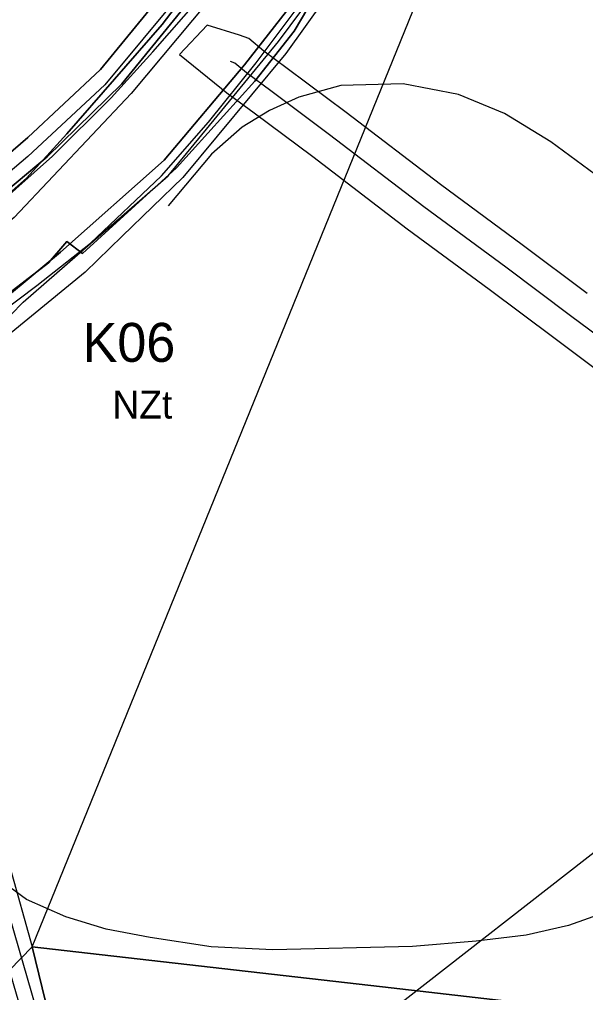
# Model space of a CAD drawing. Extents: x -758499 to -754160, y -1175205 to -1172032.
# Drawn here: x -756267 to -756063.4, y -1173950.7 to -1173601 of the extents above; entities that cross this region are included whole.
import ezdxf

# ---------------------------------------------------------------- set-up
doc = ezdxf.new("R2010")
doc.units = 0
for name, color, linetype in [('A012_RegLidArch_p', 7, 'Continuous'), ('A041_BPEJ_p', 7, 'Continuous'), ('A051_QAZ_p', 7, 'Continuous'), ('A068_Vodovod_l', 7, 'Continuous'), ('D cyklocesty NÁVRH', 7, 'Continuous'), ('HRANICE změn v krajině', 7, 'Continuous'), ('indexy RZV_TYP_2', 7, 'Continuous'), ('indexy změn v krajině', 7, 'Continuous'), ('LIMITY BP vodovodu', 7, 'Continuous'), ('NÁVRH NZt zeměděl-trvalý travní porost', 7, 'Continuous'), ('PLOCHY NZo zemědělské-orná půda', 7, 'Continuous'), ('PLOCHY NZt zeměděl-trvalý travní porost', 7, 'Continuous'), ('PLOCHY PV prostranství veřejné', 7, 'Continuous'), ('PLOCHY VV vodní a vodohospodářské', 7, 'Continuous'), ('vrstevnice', 7, 'Continuous'), ('ÚSES NBK funkční', 7, 'Continuous')]:
    doc.layers.add(name, color=color, linetype=linetype)

msp = doc.modelspace()

# ---------------------------------------------------------------- linework, layer by layer
at = {"layer": 'A012_RegLidArch_p'}
msp.add_line((-756199.2, -1173594.63), (-756226.83, -1173627.57), dxfattribs=at)
msp.add_lwpolyline([(-756226.83, -1173627.57), (-756268.88, -1173672.22), (-756311.5, -1173707.44)], dxfattribs=at)
at = {"layer": 'A041_BPEJ_p'}
for p, q in [((-756116.22, -1173517.99), (-756168.24, -1173605.24)), ((-756168.24, -1173605.24), (-756116.22, -1173517.99)), ((-756173.39, -1173546.71), (-756215.65, -1173602.8)), ((-756215.65, -1173602.8), (-756173.39, -1173546.71)), ((-756215.65, -1173602.8), (-756250, -1173642.09)), ((-756250, -1173642.09), (-756215.65, -1173602.8)), ((-756168.24, -1173605.24), (-756182.33, -1173623.12)), ((-756182.33, -1173623.12), (-756168.24, -1173605.24)), ((-756182.33, -1173623.12), (-756210.51, -1173654.28)), ((-756210.51, -1173654.28), (-756182.33, -1173623.12)), ((-756250, -1173642.09), (-756264.42, -1173658.07)), ((-756264.42, -1173658.07), (-756250, -1173642.09)), ((-756210.51, -1173654.28), (-756244.37, -1173685.17)), ((-756244.37, -1173685.17), (-756210.51, -1173654.28)), ((-756264.42, -1173658.07), (-756281.49, -1173672.97)), ((-756281.49, -1173672.97), (-756264.42, -1173658.07)), ((-756250, -1173680.83), (-756256.57, -1173688.42)), ((-756256.57, -1173688.42), (-756250, -1173680.83)), ((-756244.37, -1173685.17), (-756250, -1173680.83)), ((-756250, -1173680.83), (-756244.37, -1173685.17)), ((-756256.57, -1173688.42), (-756289.62, -1173713.89)), ((-756289.62, -1173713.89), (-756256.57, -1173688.42))]:
    msp.add_line(p, q, dxfattribs=at)
at = {"layer": 'A051_QAZ_p'}
msp.add_line((-756152.25, -1173971.84), (-756013, -1173863.34), dxfattribs=at)
at = {"layer": 'A068_Vodovod_l'}
for p, q in [((-756189.54, -1173616.65), (-756191.07, -1173616.14)), ((-756185.37, -1173620.22), (-756189.54, -1173616.65)), ((-756176.64, -1173626.65), (-756185.37, -1173620.22)), ((-756155.5, -1173642.4), (-756176.64, -1173626.65)), ((-756121.51, -1173668.32), (-756155.5, -1173642.4)), ((-756092.09, -1173690.05), (-756121.51, -1173668.32)), ((-756068.78, -1173707.48), (-756092.09, -1173690.05)), ((-756032.27, -1173734.88), (-756068.78, -1173707.48))]:
    msp.add_line(p, q, dxfattribs=at)
at = {"layer": 'D cyklocesty NÁVRH'}
for points in [[(-756249.6, -1173995.8), (-756304.39, -1173806.64), (-756305.26, -1173790.41), (-756304.1, -1173771.42), (-756294.53, -1173742.29), (-756274.67, -1173711.7), (-756265.69, -1173702.57), (-756213.5, -1173657.2), (-756173.79, -1173608.93), (-756149, -1173575.45), (-756123.93, -1173539.07), (-756113.78, -1173523.85), (-756096.39, -1173481.53), (-756089.28, -1173456.16), (-756083.34, -1173400.06), (-756087.11, -1173376.87), (-756109.72, -1173340.64), (-756134.36, -1173306.72), (-756197.27, -1173242.94), (-756214.08, -1173227), (-756241.33, -1173219.46)], [(-756209.01, -1173591.54), (-756236.26, -1173624.44), (-756263.95, -1173650.25), (-756296.12, -1173677.5), (-756357.8, -1173719.17), (-756436.94, -1173759.46), (-756454.77, -1173769.9), (-756472.6, -1173784.4), (-756491.3, -1173803.96), (-756508.33, -1173830.05), (-756526.01, -1173874.7), (-756528.77, -1173902.46), (-756530.07, -1173928.4), (-756522.17, -1173968.91)]]:
    msp.add_lwpolyline(points, dxfattribs=at)
at = {"layer": 'HRANICE změn v krajině'}
msp.add_lwpolyline([(-756077.06, -1173478.96), (-756089.31, -1173477.45), (-756108.45, -1173524.92), (-756114.41, -1173533.36), (-756130.83, -1173556.6), (-756150.28, -1173583.99), (-756171.25, -1173613.25), (-756208.27, -1173657.74), (-756230.07, -1173678.85), (-756243.43, -1173691.79), (-756270.02, -1173713.57), (-756287.28, -1173738.82), (-756299.86, -1173772.51), (-756300.9, -1173783.62), (-756300.38, -1173803.34), (-756295.66, -1173826.96), (-756287.36, -1173853.3), (-756275.83, -1173888.32), (-756270.44, -1173905.55), (-756262.48, -1173934.3)], close=True, dxfattribs=at)
msp.add_lwpolyline([(-756186.45, -1173556.18), (-756237.88, -1173619.03), (-756264.01, -1173643.38), (-756303.51, -1173677.48)], dxfattribs=at)
at = {"layer": 'LIMITY BP vodovodu'}
for points in [[(-756062.78, -1173699.48), (-756086.13, -1173682.02), (-756115.51, -1173660.32), (-756149.48, -1173634.41), (-756170.69, -1173618.61), (-756179.14, -1173612.39), (-756184.52, -1173607.78), (-756187.91, -1173606.65), (-756199.45, -1173603.04), (-756209.45, -1173613.62), (-756191.87, -1173627.82)], [(-755737.24, -1173966.34), (-755737.52, -1173966.03), (-755743.8, -1173961.27), (-755751.56, -1173955.53), (-755764.96, -1173945.47), (-755777.83, -1173935.97), (-755788.04, -1173928.39), (-755794.83, -1173923.31), (-755810.74, -1173911.3), (-755854.87, -1173878.89), (-755860.39, -1173874.99), (-755873.42, -1173865.41), (-755890.92, -1173852.32), (-755925.44, -1173826.27), (-755961.16, -1173799.77), (-756002.08, -1173769.43), (-756038.23, -1173742.91), (-756074.78, -1173715.48), (-756098.05, -1173698.08), (-756127.51, -1173676.32), (-756161.52, -1173650.39), (-756182.59, -1173634.69), (-756191.6, -1173628.05), (-756191.87, -1173627.82)]]:
    msp.add_lwpolyline(points, dxfattribs=at)
at = {"layer": 'NÁVRH NZt zeměděl-trvalý travní porost'}
msp.add_lwpolyline([(-756077.06, -1173478.96), (-756089.31, -1173477.45), (-756108.45, -1173524.92), (-756114.41, -1173533.36), (-756130.83, -1173556.6), (-756150.28, -1173583.99), (-756171.25, -1173613.25), (-756208.27, -1173657.74), (-756230.07, -1173678.85), (-756243.43, -1173691.79), (-756270.02, -1173713.57), (-756287.28, -1173738.82), (-756299.86, -1173772.51), (-756300.9, -1173783.62), (-756300.38, -1173803.34), (-756295.66, -1173826.96), (-756287.36, -1173853.3), (-756275.83, -1173888.32), (-756270.44, -1173905.55), (-756262.48, -1173934.3)], close=True, dxfattribs=at)
msp.add_lwpolyline([(-756186.45, -1173556.18), (-756237.88, -1173619.03), (-756264.01, -1173643.38), (-756303.51, -1173677.48)], dxfattribs=at)
at = {"layer": 'PLOCHY NZo zemědělské-orná půda'}
msp.add_lwpolyline([(-756077.06, -1173478.96), (-755939, -1173496.02), (-755788.69, -1173514.59), (-755803.13, -1173571.82), (-755805.75, -1173585.48), (-755807.33, -1173596.57), (-755811.48, -1173625.85), (-755816.23, -1173657.13), (-755827.86, -1173728.55), (-755836.34, -1173778.88), (-755839.72, -1173794.13), (-755847.33, -1173828.42), (-755853.54, -1173858.55), (-755857.96, -1173881.04), (-755860.98, -1173905.99), (-755864.13, -1173939.19), (-755865.84, -1173955.55), (-755864.85, -1173983.31), (-756010.38, -1173963.17), (-756136.39, -1173948.74), (-756259.32, -1173934.66), (-756262.48, -1173934.3)], close=True, dxfattribs=at)
at = {"layer": 'PLOCHY NZt zeměděl-trvalý travní porost'}
msp.add_lwpolyline([(-756262.48, -1173934.3), (-756259.32, -1173934.66), (-756136.39, -1173948.74), (-756010.38, -1173963.17), (-755864.85, -1173983.31), (-755864.13, -1174003.43), (-755861.95, -1174015.18), (-756015.4, -1173990.9), (-756135.3, -1173977.35), (-756249.97, -1173964.39), (-756252.79, -1173972.31), (-756255.27, -1173963.79)], close=True, dxfattribs=at)
at = {"layer": 'PLOCHY PV prostranství veřejné'}
for points in [[(-756530.34, -1173874.29), (-756523.38, -1173856.36), (-756512.75, -1173829.54), (-756507.85, -1173821.74), (-756495.76, -1173802.52), (-756475.91, -1173781.39), (-756456.62, -1173766.62), (-756451.46, -1173763.38), (-756436.94, -1173754.28), (-756362.02, -1173716.47), (-756303.51, -1173677.48), (-756264.01, -1173643.38), (-756237.88, -1173619.03), (-756186.45, -1173556.18)], [(-756179.25, -1173561.6), (-756230.21, -1173624.17), (-756257.06, -1173650.39), (-756298.09, -1173684.69), (-756357.37, -1173724.18), (-756381.08, -1173737.25), (-756434.71, -1173763.24), (-756452.17, -1173773.29), (-756470.53, -1173787.35), (-756489.4, -1173807.43), (-756506.16, -1173834.09), (-756522.48, -1173876.15), (-756526.12, -1173914.67), (-756525.19, -1173936.17), (-756518.24, -1173968.69)], [(-756259.77, -1173979.69), (-756303.95, -1173828.7), (-756309.26, -1173804.29), (-756309.78, -1173780.01), (-756307.73, -1173764.17), (-756300.32, -1173742.2), (-756275.6, -1173703.89), (-756252.27, -1173684.6), (-756214.93, -1173651.6), (-756186.03, -1173617.26), (-756154.47, -1173576.88)], [(-756150.28, -1173583.99), (-756171.25, -1173613.25), (-756208.27, -1173657.74), (-756230.07, -1173678.85), (-756243.43, -1173691.79), (-756270.02, -1173713.57), (-756287.28, -1173738.82), (-756299.86, -1173772.51), (-756300.9, -1173783.62), (-756300.38, -1173803.34), (-756295.66, -1173826.96), (-756287.36, -1173853.3), (-756275.83, -1173888.32), (-756270.44, -1173905.55), (-756262.48, -1173934.3), (-756255.27, -1173963.79)]]:
    msp.add_lwpolyline(points, dxfattribs=at)
at = {"layer": 'PLOCHY VV vodní a vodohospodářské'}
for points in [[(-756518.24, -1173968.69), (-756525.19, -1173936.17), (-756526.12, -1173914.67), (-756522.48, -1173876.15), (-756506.16, -1173834.09), (-756489.4, -1173807.43), (-756470.53, -1173787.35), (-756452.17, -1173773.29), (-756434.71, -1173763.24), (-756381.08, -1173737.25), (-756357.37, -1173724.18), (-756298.09, -1173684.69), (-756257.06, -1173650.39), (-756230.21, -1173624.17), (-756179.25, -1173561.6)], [(-756154.47, -1173576.88), (-756186.03, -1173617.26), (-756214.93, -1173651.6), (-756252.27, -1173684.6), (-756275.6, -1173703.89), (-756293.27, -1173717.15), (-756307.55, -1173727.87), (-756335.22, -1173744.27), (-756392.7, -1173773.24), (-756429.61, -1173790.41), (-756449.31, -1173805.42), (-756466.6, -1173824.42), (-756483.37, -1173856.05), (-756496.96, -1173900.08), (-756495.29, -1173934.68), (-756484.75, -1173972.36)]]:
    msp.add_lwpolyline(points, dxfattribs=at)
at = {"layer": 'vrstevnice'}
for p, q in [((-756219.05, -1173612.66), (-756200.18, -1173591.06)), ((-756181.87, -1173616.58), (-756162.17, -1173590.19)), ((-756233.98, -1173629.17), (-756219.05, -1173612.66)), ((-756198.96, -1173637.9), (-756181.87, -1173616.58)), ((-756151.43, -1173624.68), (-756166.47, -1173628.87)), ((-756129, -1173624.1), (-756151.43, -1173624.68)), ((-756109.1, -1173627.95), (-756129, -1173624.1)), ((-756255.12, -1173650.16), (-756233.98, -1173629.17)), ((-756166.47, -1173628.87), (-756177.09, -1173633.75)), ((-756092.49, -1173634.78), (-756109.1, -1173627.95)), ((-756177.09, -1173633.75), (-756186.96, -1173639.73)), ((-756075.84, -1173644.92), (-756092.49, -1173634.78)), ((-756215.88, -1173657.19), (-756198.96, -1173637.9)), ((-756186.96, -1173639.73), (-756197.91, -1173649.4)), ((-756053.72, -1173661.32), (-756075.84, -1173644.92)), ((-756278.73, -1173671.07), (-756255.12, -1173650.16)), ((-756197.91, -1173649.4), (-756213.54, -1173667.94)), ((-756241.43, -1173681.37), (-756215.88, -1173657.19)), ((-756260.78, -1173696.64), (-756241.43, -1173681.37)), ((-756276.67, -1173708.56), (-756260.78, -1173696.64)), ((-756264.53, -1173917.3), (-756275.46, -1173909.32)), ((-756264.53, -1173917.3), (-756275.46, -1173909.32)), ((-756250.37, -1173923.52), (-756264.53, -1173917.3)), ((-756250.37, -1173923.52), (-756264.53, -1173917.3)), ((-756048.3, -1173919.13), (-756069.56, -1173926.69)), ((-756048.3, -1173919.13), (-756069.56, -1173926.69)), ((-756235.8, -1173927.98), (-756250.37, -1173923.52)), ((-756235.8, -1173927.98), (-756250.37, -1173923.52)), ((-756069.56, -1173926.69), (-756084.71, -1173930.09)), ((-756069.56, -1173926.69), (-756084.71, -1173930.09)), ((-756219.96, -1173930.95), (-756235.8, -1173927.98)), ((-756219.96, -1173930.95), (-756235.8, -1173927.98)), ((-756084.71, -1173930.09), (-756102.7, -1173932.28)), ((-756084.71, -1173930.09), (-756102.7, -1173932.28)), ((-756198.08, -1173934.32), (-756219.96, -1173930.95)), ((-756198.08, -1173934.32), (-756219.96, -1173930.95)), ((-756102.7, -1173932.28), (-756125.67, -1173934.15)), ((-756102.7, -1173932.28), (-756125.67, -1173934.15)), ((-756175.82, -1173935.39), (-756198.08, -1173934.32)), ((-756175.82, -1173935.39), (-756198.08, -1173934.32)), ((-756125.67, -1173934.15), (-756175.82, -1173935.39)), ((-756125.67, -1173934.15), (-756175.82, -1173935.39))]:
    msp.add_line(p, q, dxfattribs=at)
at = {"layer": 'ÚSES NBK funkční'}
msp.add_lwpolyline([(-756270.58, -1173942.76), (-756262.48, -1173934.3), (-756077.06, -1173478.96), (-756067.81, -1173452.32), (-756066.69, -1173440.28), (-756064.93, -1173421.23), (-756064.28, -1173390.32), (-756084.01, -1173390.53)], dxfattribs=at)

# ---------------------------------------------------------------- texts
at = {"layer": 'indexy RZV_TYP_2'}
msp.add_text('NZt', height=10, dxfattribs=at).set_placement((-756233.58, -1173744.44))
at = {"layer": 'indexy změn v krajině'}
msp.add_text('K06', height=14, dxfattribs=at).set_placement((-756244.28, -1173724.06))

doc.saveas('drawing.dxf')
